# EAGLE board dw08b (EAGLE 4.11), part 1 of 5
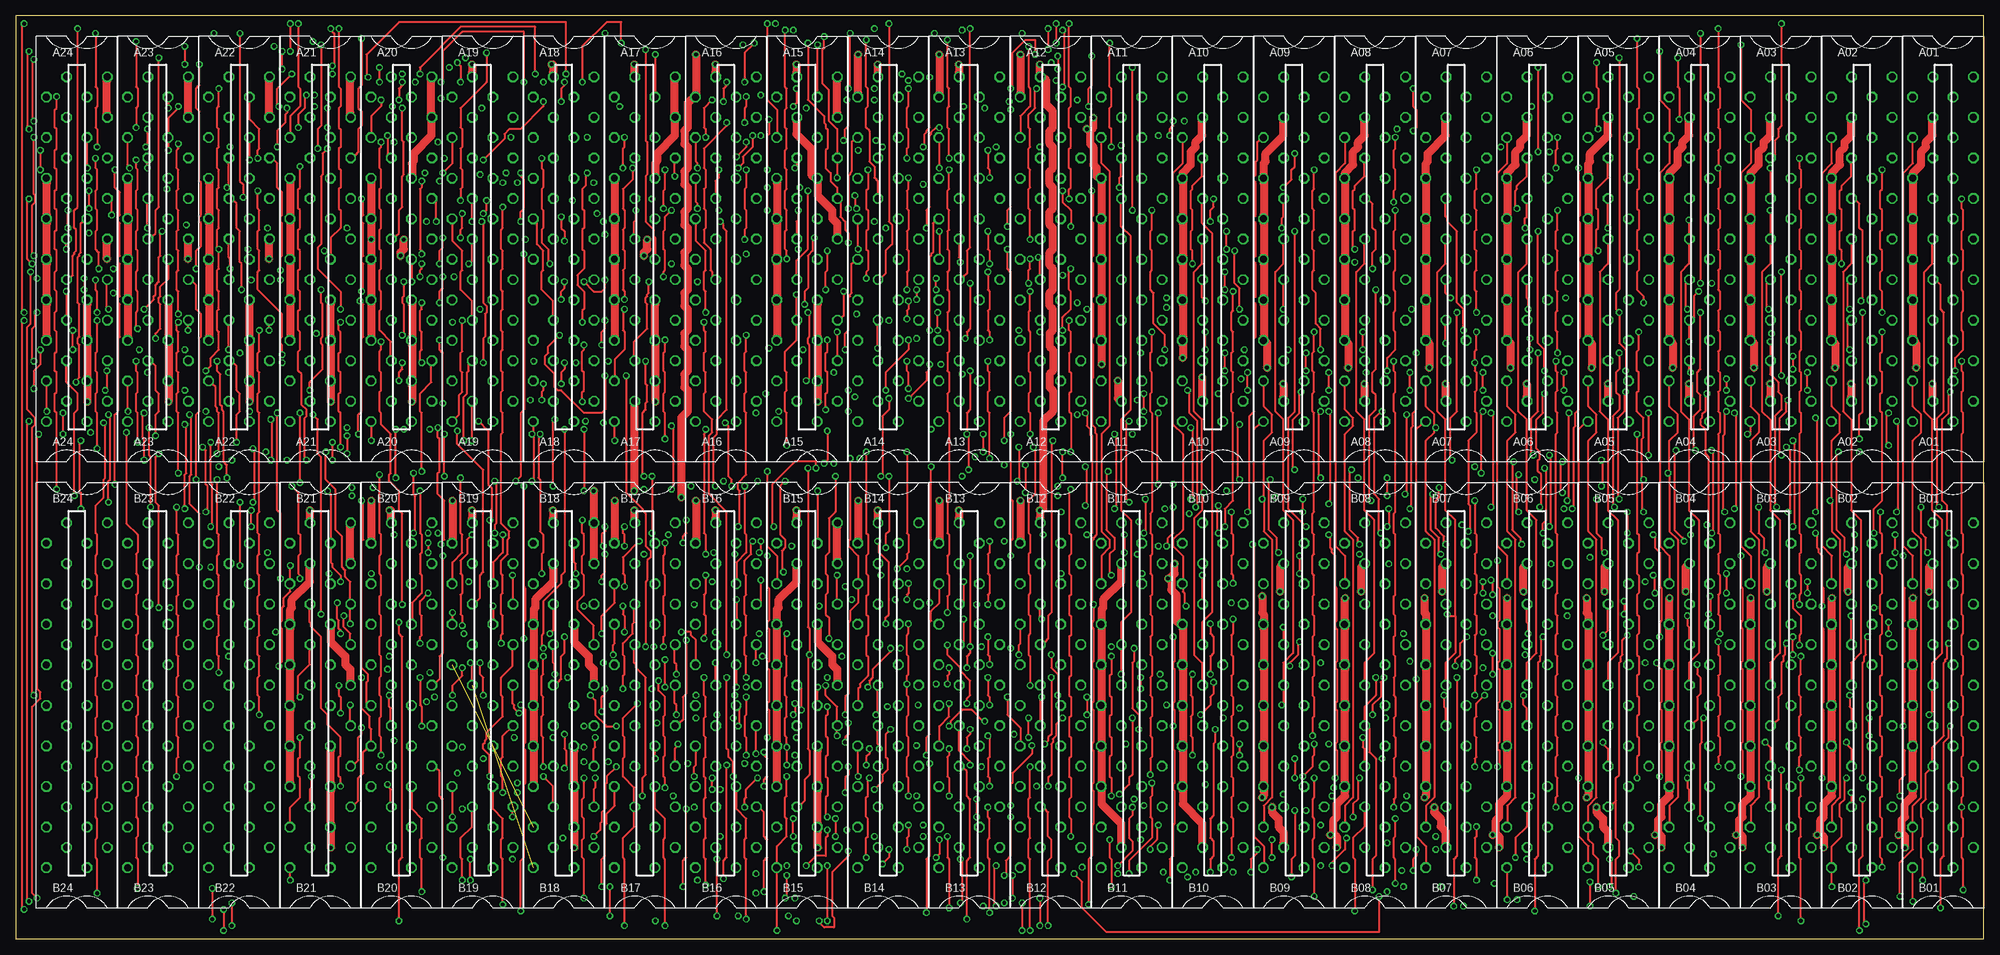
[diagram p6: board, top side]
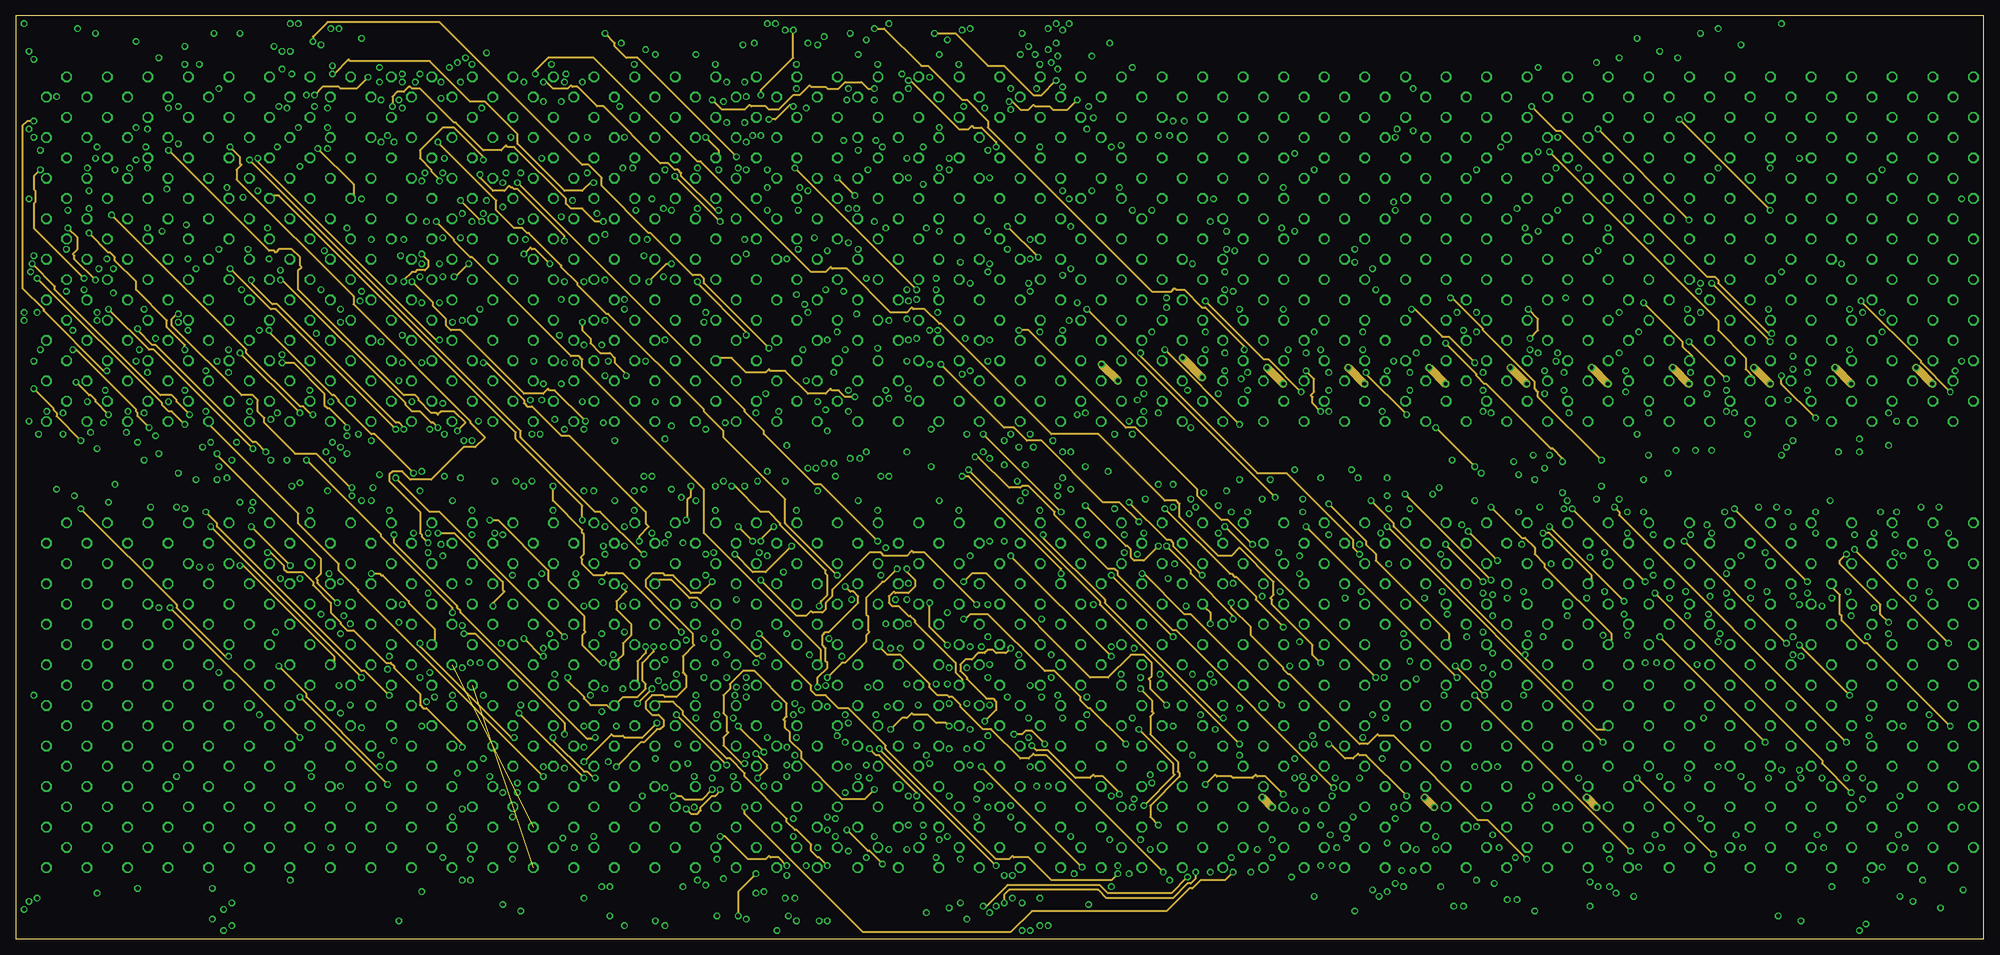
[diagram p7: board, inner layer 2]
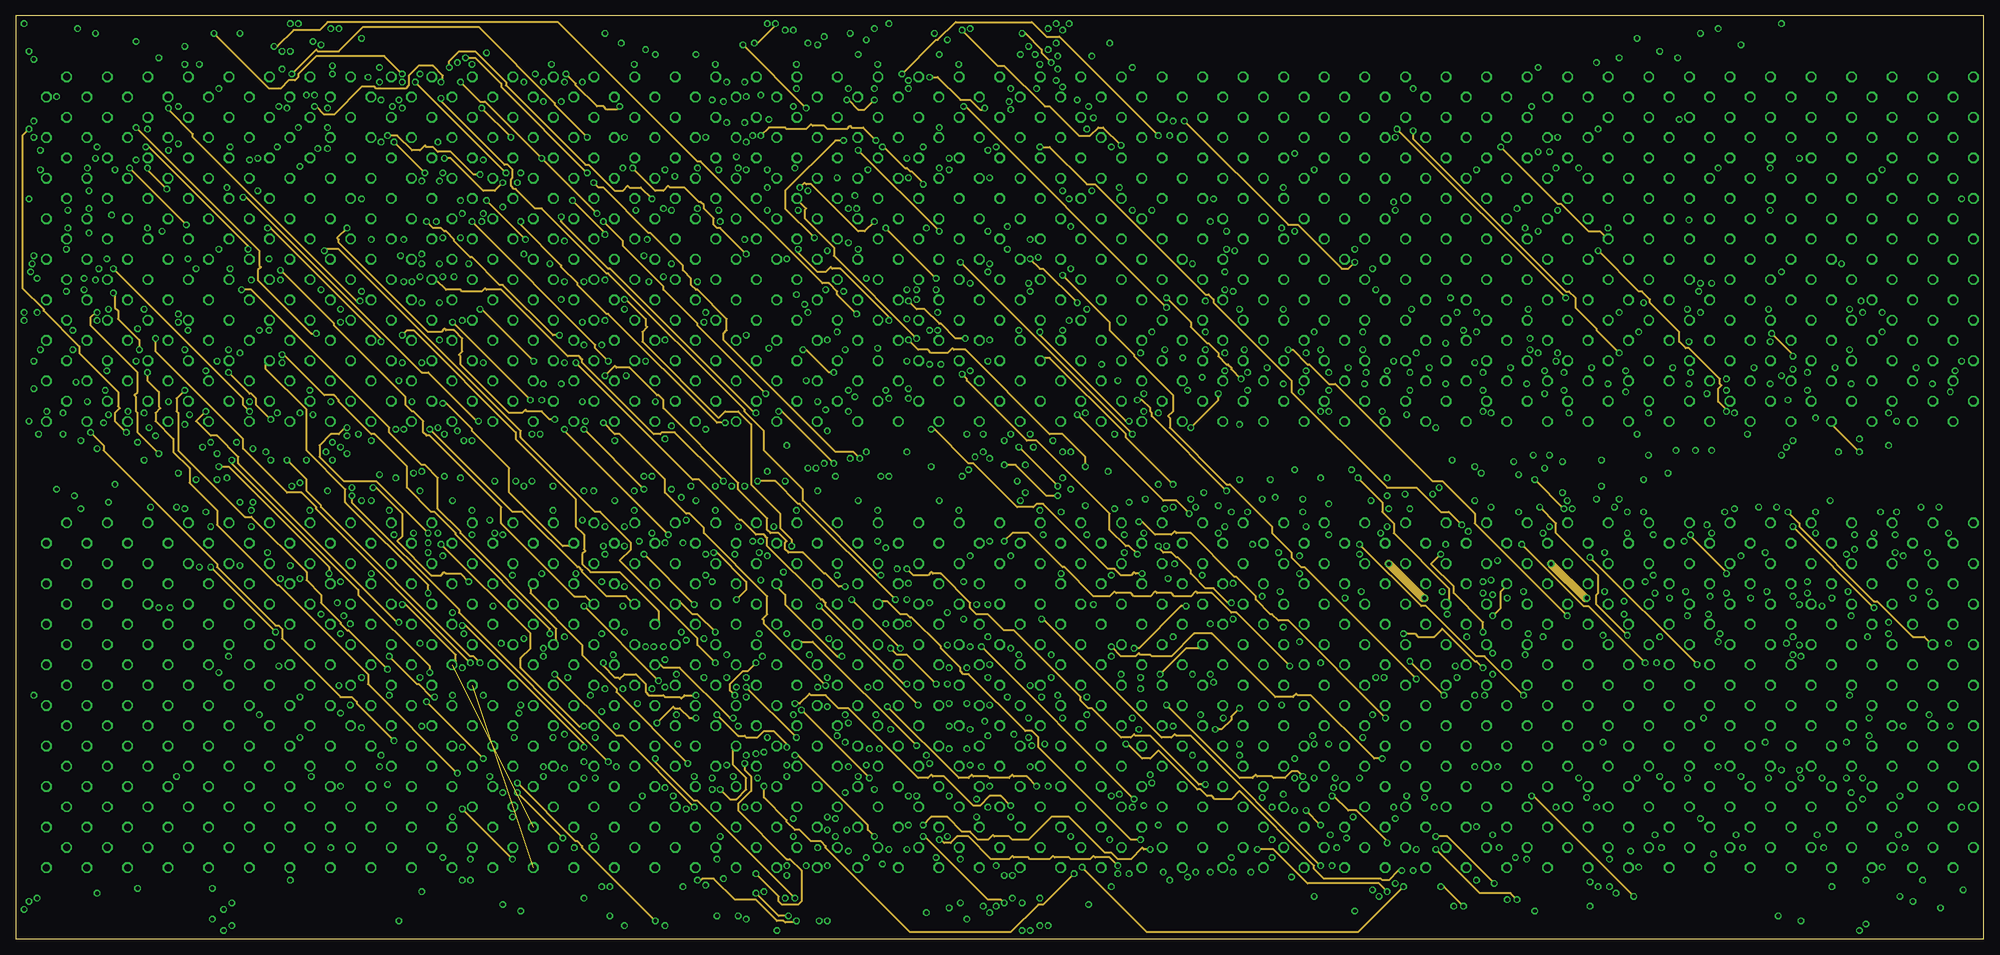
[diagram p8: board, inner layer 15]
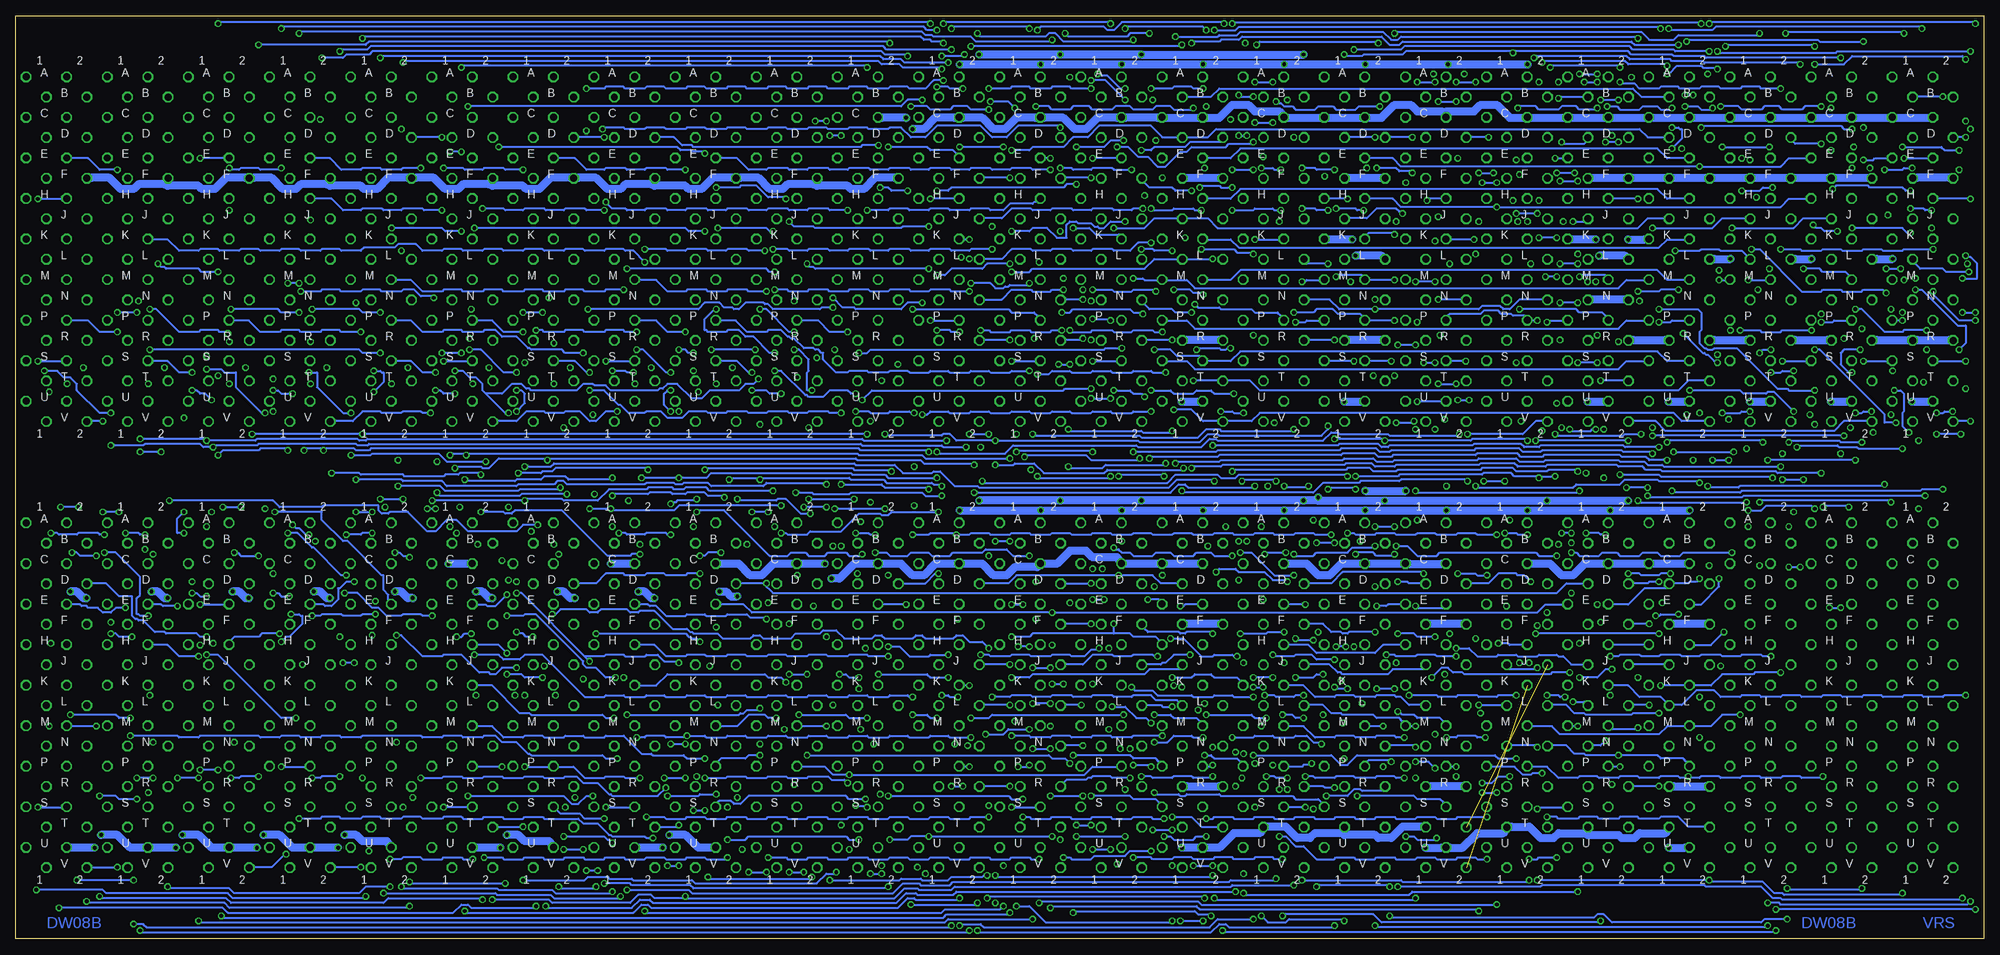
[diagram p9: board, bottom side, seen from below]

Size 307.98 x 144.46 mm. Coordinates in mm from the lower left corner, seen from the top.
Outline: 0,0 307.98,0 307.98,144.46 0,144.46 0,0
Copper layers (1*2*15*16): Top 0.035mm / dielectric 1.5mm / 2 0.035mm / dielectric 0.15mm / 15 0.035mm / dielectric 0.2mm / Bottom 0.035mm
Design rules "10mils": minimum track width 12mil, minimum drill 24mil, track to track 10mil, track to pad 10mil, pad to pad 10mil, via to via 10mil, smd to smd 10mil, copper to edge 25mil, drill to drill 10mil, minimum pad ring 10mil, minimum via ring 8mil, stop-mask expansion 0mil, vias tented up to drill 0mil, thermal gap 10mil
Net classes: 1 supply: width 1.27 mm

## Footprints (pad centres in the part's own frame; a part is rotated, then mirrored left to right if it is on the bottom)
H807 = drill 1.092 octagon: A1 4.763,28.575; A2 -1.587,28.575; B1 1.587,25.4; B2 -4.763,25.4; C1 4.763,22.225; C2 -1.587,22.225; D1 1.587,19.05; D2 -4.763,19.05; E1 4.763,15.875; E2 -1.587,15.875; F1 1.587,12.7; F2 -4.763,12.7; H1 4.763,9.525; H2 -1.587,9.525; J1 1.587,6.35; J2 -4.763,6.35; K1 4.763,3.175; K2 -1.587,3.175; L1 1.587,0; L2 -4.763,0; M1 4.763,-3.175; M2 -1.587,-3.175; N1 1.587,-6.35; N2 -4.763,-6.35; P1 4.763,-9.525; P2 -1.587,-9.525; R1 1.587,-12.7; R2 -4.763,-12.7; S1 4.763,-15.875; S2 -1.587,-15.875; T1 1.587,-19.05; T2 -4.763,-19.05; U1 4.763,-22.225; U2 -1.587,-22.225; V1 1.587,-25.4; V2 -4.763,-25.4

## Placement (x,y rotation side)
A01  W011  [H807]  301.62,106.36 0 top
A02  W011  [H807]  288.93,106.36 0 top
A03  W011  [H807]  276.23,106.36 0 top
A04  W011  [H807]  263.52,106.36 0 top
A05  W011  [H807]  250.82,106.36 0 top
A06  W011  [H807]  238.12,106.36 0 top
A07  W011  [H807]  225.43,106.36 0 top
A08  W011  [H807]  212.72,106.36 0 top
A09  W011  [H807]  200.03,106.36 0 top
A10  W011  [H807]  187.32,106.36 0 top
A11  W011  [H807]  174.62,106.36 0 top
A12  M508  [H807]  161.93,106.36 0 top
A13  M508  [H807]  149.22,106.36 0 top
A14  M508  [H807]  136.53,106.36 0 top
A15  M906  [H807]  123.83,106.36 0 top
A16  M508  [H807]  111.12,106.36 0 top
A17  M906  [H807]  98.42,106.36 0 top
A18  M660  [H807]  85.72,106.36 0 top
A19  M660  [H807]  73.03,106.36 0 top
A20  M903  [H807]  60.33,106.36 0 top
A21  M903  [H807]  47.62,106.36 0 top
A22  M903  [H807]  34.92,106.36 0 top
A23  M903  [H807]  22.23,106.36 0 top
A24  M903  [H807]  9.53,106.36 0 top
B01  W011  [H807]  301.62,36.51 0 top
B02  W011  [H807]  288.93,36.51 0 top
B03  W011  [H807]  276.23,36.51 0 top
B04  W011  [H807]  263.52,36.51 0 top
B05  W011  [H807]  250.82,36.51 0 top
B06  W011  [H807]  238.12,36.51 0 top
B07  W011  [H807]  225.43,36.51 0 top
B08  W011  [H807]  212.72,36.51 0 top
B09  W011  [H807]  200.03,36.51 0 top
B10  W011  [H807]  187.32,36.51 0 top
B11  W011  [H807]  174.62,36.51 0 top
B12  M508  [H807]  161.93,36.51 0 top
B13  M508  [H807]  149.22,36.51 0 top
B14  M508  [H807]  136.53,36.51 0 top
B15  M906  [H807]  123.83,36.51 0 top
B16  M051  [H807]  111.12,36.51 0 top
B17  M051  [H807]  98.42,36.51 0 top
B18  M906  [H807]  85.72,36.51 0 top
B19  M051  [H807]  73.03,36.51 0 top
B20  M051  [H807]  60.33,36.51 0 top
B21  M906  [H807]  47.62,36.51 0 top
B22  H807  [H807]  34.92,36.51 0 top
B23  H807  [H807]  22.23,36.51 0 top
B24  H807  [H807]  9.53,36.51 0 top

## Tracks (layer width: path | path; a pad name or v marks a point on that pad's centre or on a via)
-15V  (via drill 0.61)
  Top 1.27: v106.43,138.43 106.43,132.33 A16.B2 105.66,131.32 105.16,130.81 105.16,127 104.65,126.49 104.65,124.46 105.16,123.95 105.16,120.65 104.65,120.14 104.65,118.11 105.16,117.6 105.16,114.3 104.65,113.79 104.65,111.76 105.16,111.25 105.16,107.95 104.65,107.44 104.65,105.41 105.16,104.9 105.16,101.6 104.65,101.09 104.65,99.06 105.16,98.55 105.16,95.25 104.65,94.74 104.65,92.71 105.16,92.2 105.16,88.9 104.65,88.39 104.65,86.36 105.16,85.85 105.16,82.55 104.14,81.53 v104.14,69.09 | v131.83,138.43 131.83,132.33 A14.B2 | v144.53,138.43 144.53,132.33 A13.B2 | v157.23,138.43 157.23,132.33 A12.B2 | v55.63,68.58 55.63,62.48 B20.B2 | v68.33,68.58 68.33,62.48 B19.B2 | v93.73,68.58 93.73,62.48 B17.B2 | v106.43,68.58 106.43,62.48 B16.B2 | v131.83,68.58 131.83,62.48 B14.B2 | v144.53,68.58 144.53,62.48 B13.B2 | v157.23,68.58 157.23,62.48 B12.B2
  Bottom 1.27: v106.43,138.43 v131.83,138.43 v144.53,138.43 v157.23,138.43 | v55.63,68.58 v68.33,68.58 v93.73,68.58 104.14,68.58 | 104.14,68.58 v106.43,68.58 v131.83,68.58 v144.53,68.58 v157.23,68.58 | v104.14,69.09 104.14,68.58
GND  (via drill 0.61)
  Top 1.27: B15.A1 128.52,64.52 128.52,59.44 B15.C1 | B15.K1 128.52,40.39 128.52,42.16 127.76,42.93 127.76,44.2 125.48,46.48 125.48,48.51 B15.F1 | v125.48,14.22 125.48,16.76 B15.T1 125.48,18.03 125.48,23.11 B15.R1 125.48,24.38 125.48,29.46 B15.N1 | B15.R2 119.13,24.38 119.13,29.46 B15.N2 119.13,30.73 119.13,35.81 B15.L2 119.13,37.08 119.13,42.16 B15.J2 119.13,43.43 119.13,48.51 B15.F2 119.13,49.78 119.13,51.56 119.38,51.82 119.38,53.09 122.17,55.88 122.17,58.17 B15.C2 | B21.A1 52.32,64.52 52.32,59.44 B21.C1 | B21.K1 52.32,40.39 52.32,42.16 51.56,42.93 51.56,44.2 49.28,46.48 49.28,48.51 B21.F1 | v49.28,14.22 49.28,16.76 B21.T1 49.28,18.03 49.28,23.11 B21.R1 49.28,24.38 49.28,29.46 B21.N1 | B21.R2 42.93,24.38 42.93,29.46 B21.N2 42.93,30.73 42.93,35.81 B21.L2 42.93,37.08 42.93,42.16 B21.J2 42.93,43.43 42.93,48.51 B21.F2 42.93,49.78 42.93,51.56 43.18,51.82 43.18,53.09 45.97,55.88 45.97,58.17 B21.C2 | B18.C1 90.42,59.44 90.42,64.52 B18.A1 90.42,65.79 v90.42,70.1 | B18.K1 90.42,40.39 90.42,42.16 89.66,42.93 89.66,44.2 87.38,46.48 87.38,48.51 B18.F1 | v87.38,14.22 87.38,16.76 B18.T1 87.38,18.03 87.38,23.11 B18.R1 87.38,24.38 87.38,29.46 B18.N1 | B18.R2 81.03,24.38 81.03,29.46 B18.N2 81.03,30.73 81.03,35.81 B18.L2 81.03,37.08 81.03,42.16 B18.J2 81.03,43.43 81.03,48.51 B18.F2 81.03,49.78 81.03,51.56 81.28,51.82 81.28,53.09 84.07,55.88 84.07,58.17 B18.C2 | v295.66,14.22 295.66,16 295.15,16.51 | 295.15,16.51 295.15,18.54 295.66,19.05 295.66,21.08 296.93,22.35 296.93,23.11 B01.R2 296.93,24.38 296.93,29.46 B01.N2 296.93,30.73 296.93,35.81 B01.L2 296.93,37.08 296.93,42.16 B01.J2 296.93,43.43 296.93,48.51 B01.F2 296.93,49.78 v296.93,53.34
  Top 1.27: v299.47,54.36 299.47,58.17 B01.C2 | v282.96,14.22 282.96,16 282.45,16.51 | 282.45,16.51 282.45,18.54 282.96,19.05 282.96,21.08 284.23,22.35 284.23,23.11 B02.R2 284.23,24.38 284.23,29.46 B02.N2 284.23,30.73 284.23,35.81 B02.L2 284.23,37.08 284.23,42.16 B02.J2 284.23,43.43 284.23,48.51 B02.F2 284.23,49.78 v284.23,53.34 | v286.77,54.36 286.77,58.17 B02.C2 | v270.26,14.22 270.26,16 269.75,16.51 | 269.75,16.51 269.75,18.54 270.26,19.05 270.26,21.08 271.53,22.35 271.53,23.11 B03.R2 271.53,24.38 271.53,29.46 B03.N2 271.53,30.73 271.53,35.81 B03.L2 271.53,37.08 271.53,42.16 B03.J2 271.53,43.43 271.53,48.51 B03.F2 271.53,49.78 v271.53,53.34 | v274.07,54.36 274.07,58.17 B03.C2 | v247.4,20.57 247.4,19.81 248.41,18.8 248.41,17.53 249.17,16.76 249.17,14.99 B05.U2 | v245.87,22.1 246.13,22.35 246.13,23.11 B05.R2 246.13,24.38 246.13,29.46 B05.N2 246.13,30.73 246.13,35.81 B05.L2 246.13,37.08 246.13,42.16 B05.J2 246.13,43.43 246.13,48.51 B05.F2 246.13,49.78 246.13,50.8 245.87,51.05 v245.87,53.34 | v248.67,54.36 248.67,58.17 B05.C2 | v257.56,14.22 257.56,16 257.05,16.51 | 257.05,16.51 257.05,18.54 257.56,19.05 257.56,21.08 258.83,22.35 258.83,23.11 B04.R2 258.83,24.38 258.83,29.46 B04.N2 258.83,30.73 258.83,35.81 B04.L2 258.83,37.08 258.83,42.16 B04.J2 258.83,43.43 258.83,48.51 B04.F2 258.83,49.78 v258.83,53.34 | v261.37,54.36 261.37,58.17 B04.C2 | v256.54,16.26 257.05,16.51 | v269.24,16.26 269.75,16.51 | v281.94,16.26 282.45,16.51 | v294.64,16.26 295.15,16.51 | B11.U2 172.97,14.99 172.97,18.03 169.93,21.08 169.93,23.11 B11.R2 169.93,24.38 169.93,29.46 B11.N2 169.93,30.73 169.93,35.81 B11.L2 169.93,37.08 169.93,42.16 B11.J2 169.93,43.43 169.93,48.51 B11.F2 169.93,49.78 169.93,51.56 170.18,51.82 170.18,53.09 172.97,55.88 172.97,58.17 B11.C2
  Top 1.27: v222,20.57 222,19.81 223.01,18.8 223.01,17.53 223.77,16.76 223.77,14.99 B07.U2 | v220.47,22.1 220.73,22.35 220.73,23.11 B07.R2 220.73,24.38 220.73,29.46 B07.N2 220.73,30.73 220.73,35.81 B07.L2 220.73,37.08 220.73,42.16 B07.J2 220.73,43.43 220.73,48.51 B07.F2 220.73,49.78 220.73,50.8 220.47,51.05 v220.47,53.34 | v223.27,54.36 223.27,58.17 B07.C2 | v232.16,14.22 232.16,16 231.65,16.51 | 231.65,16.51 231.65,18.54 232.16,19.05 232.16,21.08 233.43,22.35 233.43,23.11 B06.R2 233.43,24.38 233.43,29.46 B06.N2 233.43,30.73 233.43,35.81 B06.L2 233.43,37.08 233.43,42.16 B06.J2 233.43,43.43 233.43,48.51 B06.F2 233.43,49.78 v233.43,53.34 | v235.97,54.36 235.97,58.17 B06.C2 | v231.14,16.26 231.65,16.51 | v206.76,14.22 206.76,16 206.25,16.51 | 206.25,16.51 206.25,18.54 206.76,19.05 206.76,21.08 208.03,22.35 208.03,23.11 B08.R2 208.03,24.38 208.03,29.46 B08.N2 208.03,30.73 208.03,35.81 B08.L2 208.03,37.08 208.03,42.16 B08.J2 208.03,43.43 208.03,48.51 B08.F2 208.03,49.78 v208.03,53.34 | v210.57,54.36 210.57,58.17 B08.C2 | B10.U2 185.67,14.99 185.67,18.03 182.63,21.08 182.63,23.11 B10.R2 182.63,24.38 182.63,29.46 B10.N2 182.63,30.73 182.63,35.81 B10.L2 182.63,37.08 182.63,42.16 B10.J2 182.63,43.43 182.63,48.51 B10.F2 181.86,49.53 181.61,49.78 181.61,53.85 180.85,54.61 180.85,56.39 | v196.6,20.57 196.6,19.81 197.61,18.8 197.61,17.53 198.37,16.76 198.37,14.99 B09.U2 | v195.07,22.1 195.33,22.35 195.33,23.11 B09.R2 195.33,24.38 195.33,29.46 B09.N2 195.33,30.73 195.33,35.81 B09.L2 195.33,37.08 195.33,42.16 B09.J2 195.33,43.43 195.33,48.51 B09.F2 195.33,49.78 195.33,50.8 195.07,51.05 v195.07,53.59
  Top 1.27: v197.87,54.36 197.87,58.17 B09.C2 | 180.85,56.39 180.85,56.64 181.36,57.15 v181.36,58.67 | v205.74,16.26 206.25,16.51 | v180.34,56.39 180.85,56.39 | A17.A1 103.12,134.37 103.12,129.29 A17.C1 103.12,128.02 103.12,125.73 100.33,122.94 100.33,121.67 100.08,121.41 100.08,119.63 A17.F1 | v100.08,84.07 100.08,86.61 A17.T1 100.08,87.88 100.08,92.96 A17.R1 100.08,94.23 100.08,99.31 A17.N1 | A17.R2 93.73,94.23 93.73,99.31 A17.N2 93.73,100.58 93.73,105.66 A17.L2 93.73,106.93 93.73,112.01 A17.J2 93.73,113.28 93.73,118.36 A17.F2 | v98.81,109.47 98.81,107.95 98.3,107.44 v98.3,106.93 | A24.A1 14.22,134.37 14.22,129.29 A24.C1 | A23.A1 26.92,134.37 26.92,129.29 A23.C1 | A22.A1 39.62,134.37 39.62,129.29 A22.C1 | A21.A1 52.32,134.37 52.32,129.29 A21.C1 | A20.A1 65.02,134.37 65.02,129.29 A20.C1 65.02,128.02 65.02,125.73 62.23,122.94 62.23,121.67 61.98,121.41 61.98,119.63 A20.F1 | A20.F2 55.63,118.36 55.63,113.28 A20.J2 55.63,112.01 v55.63,109.47 55.63,106.93 A20.L2 55.63,105.66 55.63,100.58 A20.N2 55.63,99.31 55.63,94.23 A20.R2 | v61.98,84.07 61.98,86.61 A20.T1 61.98,87.88 61.98,92.96 A20.R1 61.98,94.23 61.98,99.31 A20.N1 | v49.28,84.07 49.28,86.61 A21.T1 49.28,87.88 49.28,92.96 A21.R1 49.28,94.23 49.28,99.31 A21.N1 | v60.71,109.47 60.71,107.95 60.2,107.44 v60.2,106.93 | v36.58,84.07 36.58,86.61 A22.T1 36.58,87.88 36.58,92.96 A22.R1 36.58,94.23 36.58,99.31 A22.N1 | A21.R2 42.93,94.23 42.93,99.31 A21.N2 42.93,100.58 42.93,105.66 A21.L2 42.93,106.93 42.93,112.01 A21.J2 42.93,113.28 42.93,118.36 A21.F2 | v39.62,106.43 39.62,108.97 A22.K1 | v23.88,84.07 23.88,86.61 A23.T1 23.88,87.88 23.88,92.96 A23.R1 23.88,94.23 23.88,99.31 A23.N1
  Top 1.27: A22.R2 30.23,94.23 30.23,99.31 A22.N2 30.23,100.58 30.23,105.66 A22.L2 30.23,106.93 30.23,112.01 A22.J2 30.23,113.28 30.23,118.36 A22.F2 | v26.92,106.43 26.92,108.97 A23.K1 | v11.18,84.07 11.18,86.61 A24.T1 11.18,87.88 11.18,92.96 A24.R1 11.18,94.23 11.18,99.31 A24.N1 | A24.R2 4.83,94.23 4.83,99.31 A24.N2 4.83,100.58 4.83,105.66 A24.L2 4.83,106.93 4.83,112.01 A24.J2 4.83,113.28 4.83,118.36 A24.F2 | A23.R2 17.53,94.23 17.53,99.31 A23.N2 17.53,100.58 17.53,105.66 A23.L2 17.53,106.93 17.53,112.01 A23.J2 17.53,113.28 17.53,118.36 A23.F2 | v14.22,106.43 14.22,108.97 A24.K1 | v287.27,86.87 287.27,84.84 A02.U2 | v284.73,89.41 284.73,93.22 A02.R2 284.23,94.23 284.23,99.31 A02.N2 284.23,100.58 284.23,105.66 A02.L2 284.23,106.93 284.23,112.01 A02.J2 284.23,113.28 284.23,118.36 A02.F2 284.23,119.63 284.23,119.89 285.5,121.16 285.5,123.19 286.26,123.95 286.26,124.71 287.27,125.73 287.27,128.02 A02.C2 | v299.97,86.87 299.97,84.84 A01.U2 | v297.43,89.41 297.43,93.22 A01.R2 296.93,94.23 296.93,99.31 A01.N2 296.93,100.58 296.93,105.66 A01.L2 296.93,106.93 296.93,112.01 A01.J2 296.93,113.28 296.93,118.36 A01.F2 296.93,119.63 296.93,119.89 298.2,121.16 298.2,123.19 298.96,123.95 298.96,124.71 299.97,125.73 299.97,128.02 A01.C2 | v261.87,86.87 261.87,84.84 A04.U2 | v259.33,89.41 259.33,93.22 A04.R2 258.83,94.23 258.83,99.31 A04.N2 258.83,100.58 258.83,105.66 A04.L2 258.83,106.93 258.83,112.01 A04.J2 258.83,113.28 258.83,118.36 A04.F2 258.83,119.63 258.83,119.89 260.1,121.16 260.1,123.19 260.86,123.95 260.86,124.71 261.87,125.73 261.87,128.02 A04.C2
  Top 1.27: v274.57,86.87 274.57,84.84 A03.U2 | v272.03,89.41 272.03,93.22 A03.R2 271.53,94.23 271.53,99.31 A03.N2 271.53,100.58 271.53,105.66 A03.L2 271.53,106.93 271.53,112.01 A03.J2 271.53,113.28 271.53,118.36 A03.F2 271.53,119.63 271.53,119.89 272.8,121.16 272.8,123.19 273.56,123.95 273.56,124.71 274.57,125.73 274.57,128.02 A03.C2 | v236.47,86.87 236.47,84.84 A06.U2 | v233.93,89.41 233.93,93.22 A06.R2 233.43,94.23 233.43,99.31 A06.N2 233.43,100.58 233.43,105.66 A06.L2 233.43,106.93 233.43,112.01 A06.J2 233.43,113.28 233.43,118.36 A06.F2 233.43,119.63 233.43,119.89 234.7,121.16 234.7,123.19 235.46,123.95 235.46,124.71 236.47,125.73 236.47,128.02 A06.C2 | v249.17,86.87 249.17,84.84 A05.U2 | v246.63,89.41 246.63,93.22 A05.R2 246.13,94.23 246.13,99.31 A05.N2 246.13,100.58 246.13,105.66 A05.L2 246.13,106.93 246.13,112.01 A05.J2 246.13,113.28 246.13,118.36 A05.F2 246.13,119.63 246.13,121.41 246.38,121.67 246.38,122.94 249.17,125.73 249.17,128.02 A05.C2 | v211.07,86.87 211.07,84.84 A08.U2 | v208.53,89.41 208.53,93.22 A08.R2 208.03,94.23 208.03,99.31 A08.N2 208.03,100.58 208.03,105.66 A08.L2 208.03,106.93 208.03,112.01 A08.J2 208.03,113.28 208.03,118.36 A08.F2 208.03,119.63 208.03,119.89 209.3,121.16 209.3,123.19 210.06,123.95 210.06,124.71 211.07,125.73 211.07,128.02 A08.C2 | v223.77,86.87 223.77,84.84 A07.U2 | v221.23,89.41 221.23,93.22 A07.R2 220.73,94.23 220.73,99.31 A07.N2 220.73,100.58 220.73,105.66 A07.L2 220.73,106.93 220.73,112.01 A07.J2 220.73,113.28 220.73,118.36 A07.F2 220.73,119.63 220.73,121.41 220.98,121.67 220.98,122.94 223.77,125.73 223.77,128.02 A07.C2
  Top 1.27: v185.67,87.88 185.67,84.84 A10.U2 | v182.63,90.93 182.63,92.96 A10.R2 182.63,94.23 182.63,99.31 A10.N2 182.63,100.58 182.63,105.66 A10.L2 182.63,106.93 182.63,112.01 A10.J2 182.63,113.28 182.63,118.36 A10.F2 182.63,119.63 182.63,119.89 183.9,121.16 183.9,123.19 184.66,123.95 184.66,124.71 185.67,125.73 185.67,128.02 A10.C2 | v198.37,86.87 198.37,84.84 A09.U2 | v195.83,89.41 195.83,93.22 A09.R2 195.33,94.23 195.33,99.31 A09.N2 195.33,100.58 195.33,105.66 A09.L2 195.33,106.93 195.33,112.01 A09.J2 195.33,113.28 195.33,118.36 A09.F2 195.33,119.63 195.33,121.41 195.58,121.67 195.58,122.94 198.37,125.73 198.37,128.02 A09.C2 | v172.47,87.38 172.47,84.58 A11.U2 | v169.93,89.92 169.93,92.96 A11.R2 169.93,94.23 169.93,99.31 A11.N2 169.93,100.58 169.93,105.66 A11.L2 169.93,106.93 169.93,112.01 A11.J2 169.93,113.28 169.93,118.36 A11.F2 169.16,119.38 169.16,120.65 168.66,121.16 168.66,123.95 168.15,124.46 168.15,126.49 | v168.66,128.52 168.66,127 168.15,126.49 | A15.K1 128.52,110.24 128.52,112.01 127.76,112.78 127.76,114.05 125.48,116.33 125.48,118.36 A15.F1 124.71,119.38 124.46,119.63 124.46,123.7 122.17,125.98 122.17,128.02 A15.C2 | v125.48,84.07 125.48,86.61 A15.T1 125.48,87.88 125.48,92.96 A15.R1 125.48,94.23 125.48,99.31 A15.N1 | A15.R2 119.13,94.23 119.13,99.31 A15.N2 119.13,100.58 119.13,105.66 A15.L2 119.13,106.93 119.13,112.01 A15.J2 119.13,113.28 119.13,118.36 A15.F2 | A15.A1 128.52,134.37 128.52,129.29 A15.C1 | v167.64,126.75 168.15,126.49 | v96.77,70.1 96.77,83.57 A17.U2
  2 1.27: v245.87,22.1 v247.4,20.57 | v220.47,22.1 v222,20.57 | v195.07,22.1 v196.6,20.57 | v284.73,89.41 v287.27,86.87 | v297.43,89.41 v299.97,86.87 | v259.33,89.41 v261.87,86.87 | v272.03,89.41 v274.57,86.87 | v233.93,89.41 v236.47,86.87 | v246.63,89.41 v249.17,86.87 | v208.53,89.41 v211.07,86.87 | v221.23,89.41 v223.77,86.87 | v182.63,90.93 v185.67,87.88 | v195.83,89.41 v198.37,86.87 | v169.93,89.92 v172.47,87.38
  15 1.27: v214.88,58.67 220.22,53.34 v220.47,53.34 | v240.28,58.67 245.62,53.34 v245.87,53.34
  Bottom 1.27: B15.C2 122.94,58.67 128.02,58.67 B15.C1 129.29,58.67 134.37,58.67 B14.C2 135.38,59.44 135.64,59.69 139.45,59.69 140.46,60.71 143,60.71 145.03,58.67 147.07,58.67 B13.C2 148.08,58.17 151.64,58.17 152.91,56.9 154.94,56.9 156.72,58.67 159.77,58.67 B12.C2 161.04,58.67 164.08,58.67 165.86,56.9 167.64,56.9 169.42,58.67 172.47,58.67 B11.C2 173.74,58.67 176.78,58.67 179.07,56.39 v180.34,56.39 | 100.46,16.64 100.58,16.51 104.65,16.51 105.41,15.75 107.44,15.75 109.22,17.53 112.01,17.53 B16.T1 113.03,16.76 113.28,16.51 117.35,16.51 119.63,14.22 121.67,14.22 B15.U2 122.94,14.22 v125.48,14.22 | 100.46,16.64 100.33,16.76 B17.T1 | B15.R2 119.63,23.88 124.71,23.88 B15.R1 | B15.F1 124.71,49.28 119.63,49.28 B15.F2 | B21.C2 46.74,58.67 51.82,58.67 B21.C1 53.09,58.67 58.17,58.67 B20.C2 59.44,58.67 62.48,58.67 64.26,56.9 66.04,56.9 67.82,58.67 70.87,58.67 B19.C2 | v49.28,14.22 46.74,14.22 B21.U2 | B21.R2 43.43,23.88 48.51,23.88 B21.R1 | B21.F1 48.51,49.28 43.43,49.28 B21.F2 | B18.C2 84.84,58.67 89.92,58.67 B18.C1 91.19,58.67 96.27,58.67 B17.C2 97.54,58.67 100.58,58.67 102.36,56.9 104.14,56.9 105.92,58.67 108.97,58.67 B16.C2 | 62.36,16.64 62.48,16.51 66.55,16.51 67.31,15.75 69.34,15.75 71.12,17.53 73.91,17.53 B19.T1 74.93,16.76 75.18,16.51 79.25,16.51 81.53,14.22 83.57,14.22 B18.U2 84.84,14.22 v87.38,14.22 | 62.36,16.64 62.23,16.76 B20.T1 | B18.R2 81.53,23.88 86.61,23.88 B18.R1 | B18.F1 86.61,49.28 81.53,49.28 B18.F2 | B21.T1 49.53,16.76 49.78,16.51 53.85,16.51 54.61,15.75 56.64,15.75 57.15,16.26 61.98,16.26 62.36,16.64 | 100.46,16.64 100.08,16.26 95.25,16.26 94.74,15.75 92.71,15.75 90.93,17.53 87.88,17.53 B18.T1
  Bottom 1.27: v295.66,14.22 299.47,14.22 B01.U2 | v299.47,54.36 298.45,54.36 297.43,53.34 v296.93,53.34 | v282.96,14.22 286.77,14.22 B02.U2 288.04,14.22 290.07,14.22 292.1,16.26 v294.64,16.26 | v286.77,54.36 285.75,54.36 284.73,53.34 v284.23,53.34 | v270.26,14.22 274.07,14.22 B03.U2 275.34,14.22 277.37,14.22 279.4,16.26 v281.94,16.26 | v274.07,54.36 273.05,54.36 272.03,53.34 v271.53,53.34 | v248.67,54.36 247.65,54.36 246.63,53.34 v245.87,53.34 | v257.56,14.22 261.37,14.22 B04.U2 262.64,14.22 264.67,14.22 266.7,16.26 v269.24,16.26 | v261.37,54.36 260.35,54.36 259.33,53.34 v258.83,53.34 | v256.54,16.26 254.76,16.26 253.75,15.24 249.94,15.24 249.68,14.99 B05.U2 | v223.27,54.36 222.25,54.36 221.23,53.34 v220.47,53.34 | v232.16,14.22 235.97,14.22 B06.U2 | v235.97,54.36 234.95,54.36 233.93,53.34 v233.43,53.34 | v231.14,16.26 229.36,16.26 228.35,15.24 224.54,15.24 224.28,14.99 B07.U2 | v206.76,14.22 210.57,14.22 B08.U2 | v210.57,54.36 209.55,54.36 208.53,53.34 v208.03,53.34 | B09.C2 197.87,58.67 194.82,58.67 193.04,56.9 191.26,56.9 189.48,58.67 186.44,58.67 B10.C2 185.17,58.67 v181.36,58.67 | v197.87,54.36 196.85,54.36 196.09,53.59 v195.07,53.59 | v205.74,16.26 203.2,16.26 201.17,14.22 199.14,14.22 B09.U2 | v214.88,58.67 211.84,58.67 B08.C2 | v240.28,58.67 237.24,58.67 B06.C2 | 84.58,129.29 84.84,129.54 88.65,129.54 89.66,130.56 92.2,130.56 94.23,128.52 96.27,128.52 A17.C2 97.54,128.52 102.62,128.52 A17.C1 103.89,128.52 108.97,128.52 A16.C2 109.98,129.29 110.24,129.54 114.05,129.54 115.06,130.56 117.6,130.56 119.63,128.52 121.67,128.52 A15.C2 122.94,128.52 128.02,128.52 A15.C1 129.29,128.52 134.37,128.52 A14.C2 135.64,128.52 138.68,128.52 140.46,126.75 142.24,126.75 144.02,128.52 147.07,128.52 A13.C2 148.34,128.52 151.38,128.52 153.16,126.75 154.94,126.75 156.72,128.52 159.77,128.52 A12.C2 161.04,128.52 164.08,128.52 165.86,126.75 v167.64,126.75
  Bottom 1.27: 84.58,129.29 A18.C2 | v100.08,84.07 97.54,84.07 A17.U2 | A17.R2 94.23,93.73 99.31,93.73 A17.R1 | v98.81,109.47 102.62,109.47 A17.K1 | v98.3,106.93 94.23,106.93 A17.L2 | A17.F1 99.31,119.13 94.23,119.13 A17.F2 | A24.C2 8.64,128.52 13.72,128.52 A24.C1 14.99,128.52 20.07,128.52 A23.C2 21.34,128.52 26.42,128.52 A23.C1 27.69,128.52 32.77,128.52 A22.C2 34.04,128.52 39.12,128.52 A22.C1 40.39,128.52 45.47,128.52 A21.C2 46.74,128.52 51.82,128.52 A21.C1 53.09,128.52 58.17,128.52 A20.C2 59.44,128.52 64.52,128.52 A20.C1 65.79,128.52 70.87,128.52 A19.C2 72.14,128.52 74.17,128.52 76.2,130.56 78.74,130.56 79.76,129.54 84.07,129.54 84.58,129.29 | v55.63,109.47 53.09,109.47 A21.K1 | A20.F1 61.21,119.13 56.13,119.13 A20.F2 54.86,119.13 49.78,119.13 A21.F1 48.51,119.13 43.43,119.13 A21.F2 42.16,119.13 37.08,119.13 A22.F1 35.81,119.13 30.73,119.13 A22.F2 29.46,119.13 24.38,119.13 A23.F1 23.11,119.13 18.03,119.13 A23.F2 | v61.98,84.07 59.44,84.07 A20.U2 | v49.28,84.07 46.74,84.07 A21.U2 | A20.R2 54.86,93.73 49.78,93.73 A21.R1 | v60.71,109.47 64.52,109.47 A20.K1 | v60.2,106.93 56.13,106.93 A20.L2 | A20.N1 61.21,100.08 56.13,100.08 A20.N2 | v36.58,84.07 34.04,84.07 A22.U2 | A21.R2 42.16,93.73 37.08,93.73 A22.R1 | v39.62,106.43 42.16,106.43 A21.L2 | v23.88,84.07 21.34,84.07 A23.U2 | A22.R2 29.46,93.73 24.38,93.73 A23.R1 | v26.92,106.43 29.46,106.43 A22.L2 | v11.18,84.07 8.64,84.07 A24.U2 | A24.R2 5.33,93.73 10.41,93.73 A24.R1 11.68,93.73 16.76,93.73 A23.R2 | v14.22,106.43 16.76,106.43 A23.L2 | A24.F1 10.41,119.13 5.33,119.13 A24.F2 | 284.61,118.24 284.73,118.11 288.8,118.11 289.56,117.35 291.59,117.35 293.37,119.13 296.16,119.13 A01.F2
  Bottom 1.27: 284.61,118.24 284.48,118.36 A02.F2 | 259.21,118.24 259.33,118.11 263.4,118.11 264.16,117.35 266.19,117.35 267.97,119.13 270.76,119.13 A03.F2 272.03,119.13 275.08,119.13 276.86,117.35 278.89,117.35 279.4,117.86 284.23,117.86 284.61,118.24 | 259.21,118.24 259.08,118.36 A04.F2 | 233.81,118.24 233.93,118.11 238,118.11 238.76,117.35 240.79,117.35 242.57,119.13 245.36,119.13 A05.F2 246.63,119.13 249.68,119.13 251.46,117.35 253.49,117.35 254,117.86 258.83,117.86 259.21,118.24 | 233.81,118.24 233.68,118.36 A06.F2 | 208.41,118.24 208.53,118.11 212.6,118.11 213.36,117.35 215.39,117.35 217.17,119.13 219.96,119.13 A07.F2 221.23,119.13 224.28,119.13 226.06,117.35 228.09,117.35 228.6,117.86 233.43,117.86 233.81,118.24 | 208.41,118.24 208.28,118.36 A08.F2 | 183.01,118.24 183.13,118.11 187.2,118.11 187.96,117.35 189.99,117.35 191.77,119.13 194.56,119.13 A09.F2 195.83,119.13 198.88,119.13 200.66,117.35 202.69,117.35 203.2,117.86 208.03,117.86 208.41,118.24 | 183.01,118.24 182.88,118.36 A10.F2 | v168.66,128.52 172.47,128.52 A11.C2 | v125.48,84.07 122.94,84.07 A15.U2 | A15.R2 119.63,93.73 124.71,93.73 A15.R1 | A15.F1 124.71,119.13 119.63,119.13 A15.F2 | 183.01,118.24 182.63,117.86 177.8,117.86 177.29,117.35 175.26,117.35 173.48,119.13 170.43,119.13 A11.F2 | v96.77,70.1 v90.42,70.1
N$1  (via drill 0.61)
  Top 0.305: v106.68,120.65 106.68,121.41 106.43,121.67 106.43,124.71 A16.D2 | v101.6,120.4 101.6,117.35 101.35,117.09 v101.35,114.3 | v97.03,114.05 97.03,112.52 96.77,112.27 96.77,110.24 A17.K2
  15 0.305: v87.12,115.57 92.2,110.49 v92.2,110.24
  Bottom 0.305: v87.12,115.57 86.87,115.82 84.84,115.82 A18.H2 | v92.2,110.24 92.46,110.49 96.27,110.49 96.52,110.24 A17.K2 | v106.68,120.65 104.65,120.65 104.39,120.4 v101.6,120.4 | v101.35,114.3 98.3,114.3 98.04,114.05 v97.03,114.05
N$2  (via drill 0.61)
  Top 0.305: v85.34,100.08 85.34,101.35 85.85,101.85 v85.85,102.87 | v88.9,102.87 90.42,101.35 91.69,101.35 92.2,101.85 v92.2,103.12 | v106.68,114.3 106.68,115.06 106.43,115.32 106.43,118.36 A16.F2 | v102.62,114.05 101.6,113.03 101.6,111 101.35,110.74 101.35,107.95 101.6,107.7 101.6,104.65 101.35,104.39 v101.35,103.63
  Bottom 0.305: v85.34,100.08 81.53,100.08 A18.N2 | v85.85,102.87 v88.9,102.87 | v92.2,103.12 96.27,103.12 A17.M2 97.28,103.89 101.09,103.89 v101.35,103.63 | v106.68,114.3 104.65,114.3 104.39,114.05 v102.62,114.05
N$3  (via drill 0.61)
  Top 0.305: v88.65,84.07 88.65,85.6 88.9,85.85 88.9,88.65 88.65,88.9 88.65,91.95 88.9,92.2 v88.9,92.96 | v91.69,92.96 91.69,95 92.2,95.5 v92.2,96.77 | v107.95,98.04 107.95,101.35 107.7,101.6 107.7,104.39 107.95,104.65 107.95,107.7 106.43,109.22 106.43,112.01 A16.J2
  Bottom 0.305: v88.65,84.07 84.84,84.07 A18.U2 | v88.9,92.96 v91.69,92.96 | v92.2,96.77 96.27,96.77 A17.P2 97.28,97.54 97.54,97.79 101.09,97.79 101.85,98.55 104.39,98.55 104.9,98.04 v107.95,98.04
N$4  (via drill 0.61)
  Top 0.305: v71.37,112.27 71.37,115.32 A19.H2 | v99.06,102.87 99.06,101.09 98.81,100.84 98.81,100.58 98.55,100.33 98.55,99.57 98.81,99.31 98.81,95.5 96.77,93.47 96.77,91.19 A17.S2
  2 0.305: v102.62,105.66 101.85,105.66 v99.06,102.87
  15 0.305: v71.37,112.27 90.68,92.96 90.68,92.46 v92.71,90.42
  Bottom 0.305: v92.71,90.42 96.27,90.42 A17.S2 | v102.62,105.66 105.92,105.66 A16.L2
N$5  (via drill 0.61)
  Top 0.305: v95.25,98.55 95,98.3 95,95.25 95.25,95 95.25,92.2 93.73,90.68 93.73,87.88 A17.T2
  Bottom 0.305: A16.N2 105.66,100.08 102.36,100.08 100.84,98.55 v95.25,98.55 78.99,98.55 78.49,99.06 75.69,99.06 75.18,98.55 74.17,98.55 72.64,100.08 68.83,100.08 A19.N2
N$6  (via drill 0.61)
  Top 0.305: v71.37,77.98 71.37,83.57 A19.U2 | v93.73,77.98 93.73,80.26 A17.V2 | v101.6,93.73 101.6,91.95 101.35,91.69 101.35,88.9 101.6,88.65 101.6,85.6 101.35,85.34 101.35,82.55 101.6,82.3 v101.6,78.23
  Bottom 0.305: v71.37,77.98 71.63,78.23 80.01,78.23 80.26,77.98 v93.73,77.98 93.98,78.23 v101.6,78.23 | v101.6,93.73 105.66,93.73 A16.R2
N$7  (via drill 0.61)
  Top 0.305: A19.J2 68.33,112.01 68.33,109.22 69.85,107.7 69.85,104.65 69.6,104.39 69.6,101.6 71.37,99.82 71.37,97.54 A19.P2 | A18.J2 81.53,112.27 81.53,108.71 82.55,107.7 82.55,104.65 82.3,104.39 82.3,101.6 84.07,99.82 84.07,97.54 A18.P2 | A18.V2 81.03,80.26 81.03,79.25 v80.77,78.99 81.03,78.74 81.03,71.88 v80.77,71.63 | v125.48,70.1 125.48,62.48 B15.B1 | v69.85,96.77 69.85,91.95 69.6,91.69 69.6,88.9 69.85,88.65 69.85,85.6 69.34,85.09 69.34,82.04 A19.V2
  Bottom 0.305: A18.P2 83.82,97.54 83.57,97.79 78.74,97.79 78.23,98.3 75.95,98.3 75.44,97.79 73.91,97.79 73.66,97.54 71.88,97.54 A19.P2 70.87,96.77 v69.85,96.77 | v80.77,78.99 72.14,78.99 70.1,81.03 68.83,81.03 A19.V2 | v125.48,70.1 125.22,69.85 104.9,69.85 103.38,71.37 97.79,71.37 97.54,71.63 91.44,71.63 91.19,71.88 81.03,71.88 v80.77,71.63
N_3CYCLE  (via drill 0.61)
  Top 0.305: 185.67,69.85 185.67,67.06 184.4,65.79 184.4,44.45 185.67,43.18 185.67,40.39 B10.K2 | 185.67,69.85 185.67,81.28 184.4,82.55 184.4,104.39 185.67,105.66 185.67,108.97 A10.K2 | v104.9,46.74 104.9,38.35 104.39,37.85 104.39,34.29 103.89,33.78 B17.M1 | v107.7,46.99 107.7,47.5 107.95,47.75 107.95,50.55 107.7,50.8 107.7,53.85 107.95,54.1 v107.95,56.9 | v116.33,60.45 116.59,60.71 v116.59,62.23 | v118.62,64.52 118.36,64.77 118.36,71.12 121.92,74.68 125.22,74.68 v125.22,73.66 | v185.93,69.85 185.67,69.85
  2 0.305: v116.59,62.23 116.59,62.48 v118.62,64.52
  15 0.305: v154.69,74.17 156.46,74.17 161.29,69.34 v163.07,69.34
  Bottom 0.305: v104.9,46.74 107.44,46.74 v107.7,46.99 | v107.95,56.9 111,56.9 114.55,60.45 v116.33,60.45 | v125.22,73.66 125.48,73.41 137.16,73.41 137.67,72.9 147.07,72.9 148.59,74.42 151.64,74.42 151.89,74.17 v154.69,74.17 | v163.07,69.34 165.61,69.34 166.12,69.85 177.29,69.85 177.55,69.6 183.13,69.6 183.39,69.85 v185.93,69.85
N_AC00  (via drill 0.61)
  Top 0.305: v114.05,70.87 114.05,63.5 114.3,63.25 114.3,60.45 112.78,58.93 112.78,56.13 B16.D1 | v157.99,74.17 v157.99,69.85 | v239.27,73.66 239.52,73.41 239.52,65.53 239.01,65.02 v239.01,63.5 | v241.3,125.48 241.3,123.7 241.05,123.44 v241.05,120.65 | v228.6,120.4 228.6,117.35 228.35,117.09 228.35,114.3 228.6,114.05 228.6,111 228.35,110.74 228.35,107.95 228.6,107.7 228.6,104.65 228.35,104.39 228.35,101.6 228.6,101.35 v228.6,98.04 | v225.55,98.04 225.55,82.55 224.54,81.53 224.54,75.18 v224.79,74.93
  2 0.305: v239.01,63.5 240.03,63.5 246.63,56.9 246.63,56.13 B05.D2
  Bottom 0.305: v114.05,70.87 114.3,70.61 124.46,70.61 124.97,71.12 125.98,71.12 127.25,69.85 v157.99,69.85 | v157.99,74.17 158.24,74.42 165.86,74.42 166.37,74.93 176.28,74.93 176.53,75.18 224.79,75.18 | 224.79,75.18 232.41,75.18 233.93,73.66 234.95,73.66 235.2,73.91 239.01,73.91 v239.27,73.66 | v241.3,125.48 245.36,125.48 A05.D2 | v241.05,120.65 238,120.65 237.74,120.4 234.95,120.4 234.7,120.65 231.65,120.65 231.39,120.4 v228.6,120.4 | v225.55,98.04 v228.6,98.04 | 224.79,75.18 v224.79,74.93
N_AC01  (via drill 0.61)
  Top 0.305: v267.46,66.8 267.21,67.06 267.21,78.74 267.46,78.99 267.46,82.3 v267.72,82.55 | v247.65,107.7 247.4,107.95 247.4,111 247.65,111.25 247.65,114.05 247.4,114.3 247.4,117.35 249.17,119.13 249.17,121.67 A05.E2 | v116.59,56.13 116.59,52.83 B16.E1 | v152.15,52.32 152.15,53.85 152.4,54.1 152.4,56.9 152.15,57.15 152.15,60.2 152.4,60.45 v152.4,62.23 | v199.39,42.67 199.39,43.18 200.66,44.45 200.66,46.23 v200.91,46.48 | v248.41,47.5 249.17,48.26 249.17,51.82 B05.E2
  2 0.305: v116.59,56.13 122.17,50.55 123.7,50.55 124.46,51.31 124.71,51.05 126.24,51.05 126.75,51.56 126.75,52.58 127.76,53.59 127.76,54.61 133.6,60.45 135.38,60.45 135.89,59.94 139.45,59.94 140.21,60.71 140.46,60.45 142.24,60.45 v150.37,52.32
  15 0.305: v267.72,82.55 267.72,82.8 266.45,84.07 266.45,86.11 266.95,86.61 266.7,86.87 266.7,87.63 261.87,92.46 261.37,92.46 260.35,93.47 260.35,95 255.78,99.57 255.78,100.08 254.51,101.35 254,101.35 v247.65,107.7 | v154.69,62.23 155.96,63.5 158.5,63.5 163.83,58.17 164.08,58.17 168.66,53.59 171.2,53.59 171.96,54.36 172.21,54.1 174.5,54.1 175.01,53.59 177.55,53.59 178.31,54.36 178.56,54.1 180.85,54.1 181.36,53.59 183.9,53.59 184.66,54.36 184.91,54.1 187.2,54.1 190.25,51.05 191.01,51.05 v199.39,42.67 | v217.17,47.75 218.95,47.75 219.46,47.24 222,47.24 223.27,48.51 228.35,43.43 228.6,43.43 v229.62,42.42
  Bottom 0.305: v267.46,66.8 260.1,66.8 260.1,65.53 256.79,62.23 256.03,62.23 250.7,56.9 250.44,56.9 250.44,54.61 249.68,53.85 249.68,53.09 B05.E2 | v152.15,52.32 v150.37,52.32 | v154.69,62.23 v152.4,62.23 | v200.91,46.48 201.42,46.99 202.18,46.99 202.44,47.24 202.69,47.24 203.2,47.75 v217.17,47.75 | v229.62,42.42 231.9,42.42 232.92,41.4 233.68,41.4 233.93,41.66 235.46,41.66 238.25,44.45 241.05,44.45 241.3,44.2 244.35,44.2 247.65,47.5 v248.41,47.5
N_AC02  (via drill 0.61)
  Top 0.305: v249.17,111.25 249.17,115.32 A05.H2 | v238.25,110.74 238.25,93.22 239.27,92.2 v239.27,88.9 | v230.89,82.3 231.14,82.04 231.14,67.82 v230.89,67.56 | v112.78,53.09 112.78,49.78 B16.F1 | v95.25,100.08 95.25,101.35 95,101.6 95,104.65 95.25,104.9 95.25,107.7 95,107.95 95,111 95.25,111.25 95.25,114.05 95,114.3 95,117.35 96.52,118.87 v96.52,120.65 | v139.45,97.03 139.45,98.3 139.7,98.55 v139.7,99.82 | v148.59,93.98 148.84,94.23 148.84,95 149.35,95.5 v149.35,102.62 | v158.5,102.62 158.5,104.65 158.75,104.9 v158.75,106.43
  2 0.305: v230.89,67.56 235.71,62.74 236.22,62.74 237.74,61.21 237.74,60.2 239.27,58.67 239.27,58.17 249.68,47.75 249.68,46.74 B05.H2 | v112.52,60.2 115.32,57.4 117.35,57.4 v121.41,61.47
  15 0.305: v112.78,53.09 114.3,54.61 114.3,55.88 109.73,60.45 v109.22,60.45 | v121.41,61.47 121.41,62.48 119.63,64.26 119.63,66.55 115.06,71.12 115.06,80.52 113.03,82.55 111,82.55 109.98,81.53 98.04,93.47 98.04,95 98.81,95.76 98.55,96.01 98.55,97.03 95.5,100.08 v95.25,100.08 | v96.52,120.65 100.08,117.09 101.35,117.09 102.11,117.86 102.36,117.6 104.65,117.6 106.93,115.32 107.19,115.32 107.7,114.81 107.7,114.3 109.22,112.78 109.22,111.76 109.73,111.25 110.24,111.25 v114.3,107.19 | v122.43,107.95 122.43,107.44 125.48,104.39 126.75,104.39 127.51,105.16 127.76,104.9 129.03,104.9 136.65,97.28 v136.65,96.77 | v139.7,99.82 140.97,98.55 142.24,98.55 144.53,96.27 144.78,96.27 147.07,93.98 v148.59,93.98 | v158.75,106.43 160.27,104.9 160.78,104.9 v166.12,99.57 | v180.09,100.33 183.9,96.52 183.9,95.76 186.44,93.22 186.69,93.22 188.21,91.69 188.21,91.19 189.48,89.92 189.74,89.92 190.25,89.41 190.25,89.15 v191.77,87.63
  Bottom 0.305: v249.17,111.25 241.3,111.25 240.79,110.74 v238.25,110.74 | v239.27,88.9 238,88.9 236.98,87.88 235.97,87.88 234.95,86.87 234.95,85.85 234.44,85.34 | 234.44,85.34 231.39,82.3 v230.89,82.3 | v109.22,60.45 112.27,60.45 v112.52,60.2 | v114.3,107.19 114.55,107.44 116.84,107.44 117.35,107.95 v122.43,107.95 | v136.65,96.77 136.91,97.03 v139.45,97.03 | v149.35,102.62 149.61,102.36 152.4,102.36 152.65,102.11 153.16,102.11 153.42,101.85 154.69,101.85 155.45,102.62 v158.5,102.62 | v166.12,99.57 168.4,99.57 169.42,98.55 176.53,98.55 176.78,98.81 178.56,98.81 v180.09,100.33 | v191.77,87.63 192.53,86.87 193.8,86.87 194.82,85.85 199.39,85.85 200.66,84.58 202.18,84.58 204.47,86.87 205.99,86.87 206.76,86.11 207.26,86.11 207.52,85.85 214.88,85.85 215.65,86.61 217.42,86.61 217.68,86.87 219.2,86.87 220.22,85.85 227.33,85.85 227.58,86.11 228.09,86.11 228.85,86.87 230.38,86.87 231.9,85.34 234.44,85.34
N_AC03  (via drill 0.61)
  Top 0.305: A05.K2 249.17,108.97 249.17,105.66 247.9,104.39 247.9,82.55 249.17,81.28 249.17,67.06 250.7,65.53 250.7,44.7 249.17,43.18 249.17,40.39 B05.K2 | v115.82,43.18 115.82,45.47 B16.H1 | v74.17,65.53 74.42,65.79 74.42,70.61 73.91,71.12 73.91,79.5 v72.39,81.03 | v35.56,116.08 35.56,118.11 35.05,118.62 v35.05,141.73 | v112.78,122.43 114.3,123.95 v114.3,124.71 | v163.83,117.09 163.83,115.32 165.1,114.05 v165.1,111.51 | v186.94,112.27 186.94,114.05 187.45,114.55 v187.45,115.82 | v198.37,117.6 199.64,118.87 199.64,120.4 200.15,120.9 v200.15,122.94
  2 0.305: v91.95,43.18 91.44,43.18 88.65,45.97 88.65,47.5 89.15,48.01 88.9,48.26 88.9,50.55 83.31,56.13 83.31,57.66 75.44,65.53 v74.17,65.53 | v92.2,141.73 93.73,140.21 93.73,139.7 95.5,137.92 97.28,137.92 v112.78,122.43
  15 0.305: v115.82,43.18 114.55,41.91 113.79,41.91 111.76,39.88 111.76,38.86 v112.52,38.1 | v106.43,38.1 104.65,38.1 104.14,37.59 103.89,37.85 101.6,37.85 101.35,38.1 99.06,38.1 98.55,38.61 98.55,39.88 97.03,41.4 95.25,41.4 94.49,40.64 94.23,40.89 93.73,40.89 91.95,42.67 v91.95,43.18 | v72.39,81.03 72.14,81.03 64.52,88.65 63.5,88.65 36.07,116.08 v35.56,116.08 | v135.64,123.95 135.89,123.95 139.19,120.65 139.45,120.65 139.95,120.14 140.21,120.14 141.99,118.36 v141.99,118.11 | v232.41,123.95 241.3,115.06 241.81,115.06 246.13,110.74 247.9,110.74 248.67,109.98 A05.K2
  Bottom 0.305: v112.52,38.1 111,38.1 110.74,37.85 107.95,37.85 107.7,38.1 v106.43,38.1 | v35.05,141.73 35.31,141.48 47.75,141.48 48.51,140.72 52.32,140.72 53.59,141.99 91.95,141.99 v92.2,141.73 | v114.3,124.71 114.55,124.46 118.11,124.46 118.62,123.95 123.95,123.95 124.71,123.19 125.73,123.19 128.02,120.9 129.29,120.9 130.81,122.43 132.33,122.43 133.86,123.95 v135.64,123.95 | v141.99,118.11 143.51,118.11 144.02,117.6 161.54,117.6 162.05,117.09 v163.83,117.09 | v165.1,111.51 169.16,111.51 169.42,111.25 182.88,111.25 183.13,111.51 186.18,111.51 v186.94,112.27 | v187.45,115.82 187.71,116.08 190.25,116.08 192.02,117.86 194.56,117.86 194.82,117.6 v198.37,117.6 | v200.15,122.94 200.41,123.19 202.18,123.19 202.44,123.44 203.96,123.44 204.47,123.95 v232.41,123.95
N_AC04  (via drill 0.61)
  Top 0.305: v212.09,68.58 211.84,68.83 211.84,81.79 212.85,82.8 212.85,85.09 212.34,85.6 212.34,88.65 212.85,89.15 v212.85,101.6 | v112.78,39.37 112.78,42.16 B16.J1 | v129.79,30.73 129.79,31.5 130.3,32 v130.3,33.78 | v161.54,23.88 161.54,25.15 162.05,25.65 162.05,30.48 162.31,30.73 162.31,31.24 162.81,31.75 162.81,33.53 v163.83,34.54 | v167.64,37.85 v167.64,35.05
  2 0.305: 235.97,44.2 215.65,64.52 215.65,65.02 v212.09,68.58 | 235.97,44.2 247.4,32.77 248.67,32.77 B05.M2 | v236.22,44.45 235.97,44.2
  15 0.305: v122.17,31.5 v114.3,39.37 | v136.4,36.32 147.57,25.15 149.1,25.15 149.61,25.65 149.86,25.4 152.15,25.4 152.4,25.15 155.45,25.15 155.96,25.65 156.21,25.4 158.24,25.4 v159.77,23.88
  Bottom 0.305: v212.85,101.6 215.65,101.6 215.9,101.35 218.95,101.35 219.2,101.6 222,101.6 222.25,101.35 225.3,101.35 225.55,101.6 228.35,101.6 228.6,101.35 231.65,101.35 231.9,101.6 234.7,101.6 234.95,101.35 238,101.35 238.25,101.6 241.05,101.6 241.3,101.35 244.35,101.35 246.13,103.12 248.67,103.12 A05.M2 | v114.3,39.37 v112.78,39.37 | v122.17,31.5 123.7,31.5 123.95,31.75 126.75,31.75 127.76,30.73 v129.79,30.73 | v130.3,33.78 131.06,34.54 132.59,34.54 134.37,36.32 v136.4,36.32 | v161.54,23.88 v159.77,23.88 | v163.83,34.54 164.85,34.54 165.35,35.05 v167.64,35.05 | v167.64,37.85 168.15,37.85 168.4,38.1 171.2,38.1 171.45,37.85 174.5,37.85 174.75,38.1 177.55,38.1 177.8,37.85 180.85,37.85 181.1,38.1 183.9,38.1 184.15,37.85 187.2,37.85 187.45,38.1 190.25,38.1 190.5,37.85 193.55,37.85 193.8,38.1 196.6,38.1 196.85,37.85 199.9,37.85 200.15,38.1 202.95,38.1 203.2,37.85 206.25,37.85 206.5,38.1 209.3,38.1 209.55,37.85 212.6,37.85 212.85,38.1 215.65,38.1 215.9,37.85 218.95,37.85 225.55,44.45 228.35,44.45 229.11,43.69 231.65,43.69 232.41,44.45 v236.22,44.45
N_AC05  (via drill 0.61)
  Top 0.305: v248.41,30.73 248.41,30.48 249.17,29.72 249.17,27.69 B05.P2 | v214.63,64.52 214.88,64.77 v214.88,67.31 | v218.19,67.31 218.44,67.56 218.44,80.01 218.69,80.26 218.69,82.3 219.2,82.8 v219.2,91.69 | v137.92,57.91 139.45,59.44 139.45,60.2 139.7,60.45 139.7,63.25 139.45,63.5 v139.45,76.2 | v151.38,78.99 v151.38,76.2 | v188.21,63.5 187.96,63.75 187.96,67.56 v188.21,67.82
  2 0.305: v214.63,64.52 v248.41,30.73 | v127,40.89 129.29,43.18 129.79,43.18 133.1,46.48 133.1,47.5 133.6,48.01 133.35,48.26 133.35,50.55 133.1,50.8 133.1,53.34 135.64,55.88 135.89,55.88 v137.92,57.91 | v163.58,66.8 v151.38,78.99
  Bottom 0.305: v218.19,67.31 v214.88,67.31 214.63,67.06 204.98,67.06 204.22,67.82 v188.21,67.82 | v219.2,91.69 222,91.69 222.5,92.2 227.33,92.2 227.58,92.46 227.84,92.46 229.62,94.23 231.9,94.23 232.92,95.25 234.7,95.25 234.95,95 238,95 238.25,95.25 241.05,95.25 241.3,95 244.35,95 246.13,96.77 248.67,96.77 A05.P2 | v127,40.89 123.95,40.89 123.44,41.4 120.9,41.4 120.4,40.89 116.84,40.89 116.33,40.39 B16.K1 | v139.45,76.2 139.7,76.45 151.13,76.45 v151.38,76.2 | v163.58,66.8 170.94,66.8 171.45,66.29 172.47,66.29 172.72,66.55 176.02,66.55 178.82,63.75 183.64,63.75 184.15,63.25 187.2,63.25 187.45,63.5 v188.21,63.5
N_AC06  (via drill 0.61)
  Top 0.305: 250.44,21.59 249.94,21.08 B05.S2 | 250.44,21.59 250.44,25.15 250.95,25.65 250.95,43.18 251.21,43.43 251.21,44.2 251.46,44.45 251.46,46.74 v252.22,47.5 | v238.51,67.56 238.76,67.82 238.76,72.64 238.25,73.15 238.25,74.93 238.51,75.18 238.51,76.2 238,76.71 238,81.28 239.01,82.3 239.01,85.09 v239.27,85.34 | v242.32,85.85 v242.32,88.65 | v113.03,33.27 113.28,33.53 113.28,36.07 B16.L1 | v117.09,29.21 117.09,28.7 117.6,28.19 117.6,25.4 117.09,24.89 v117.09,23.88 | v165.61,10.16 166.88,8.89 166.88,4.83 170.69,1.02 213.36,1.02 v213.36,6.6 | v250.44,7.11 250.44,12.45 250.95,12.95 250.95,15.24 250.44,15.75 250.44,21.59
  2 0.305: v117.09,29.21 v113.03,33.27
  15 0.305: v252.22,47.5 247.4,52.32 247.4,53.85 247.65,54.1 247.65,56.9 241.05,63.5 241.05,65.02 v238.51,67.56 | v117.09,23.88 117.09,22.1 120.65,18.54 120.65,18.29 121.92,17.02 122.68,17.02 124.46,15.24 125.98,15.24 126.75,14.48 126.75,14.22 139.95,1.02 155.7,1.02 160.02,5.33 160.78,5.33 v165.61,10.16
  Bottom 0.305: v239.27,85.34 241.05,85.34 241.55,85.85 v242.32,85.85 | v242.32,88.65 244.35,88.65 246.13,90.42 248.67,90.42 A05.S2 | v213.36,6.6 213.61,6.35 223.77,6.35 224.28,6.86 232.66,6.86 232.92,7.11 v250.44,7.11
N_AC07  (via drill 0.61)
  Top 0.305: A05.T2 246.13,86.61 246.13,83.31 247.4,82.04 247.4,79.25 246.13,77.98 246.13,63.75 247.4,62.48 247.4,22.1 246.13,20.83 246.13,18.03 B05.T2 246.13,16.76 246.13,15.49 246.89,14.73 246.89,13.21 247.65,12.45 v247.65,8.13 | v115.82,28.96 115.82,32.77 B16.M1 | v116.08,25.15 114.3,23.37 114.3,22.1 114.05,21.84 v114.05,20.57 | v193.29,10.41 193.29,12.45 194.31,13.46 v194.31,13.97
  2 0.305: v115.82,28.96 117.6,27.18 117.6,26.67 v116.08,25.15 | v114.05,20.57 114.05,19.56 132.59,1.02 155.7,1.02 159,4.32 180.09,4.32 183.64,7.87 184.15,7.87 185.42,9.14 189.23,9.14 v190.5,10.41
  15 0.305: v194.31,13.97 196.85,13.97 202.18,8.64 213.36,8.64 v214.63,7.37
  Bottom 0.305: v193.29,10.41 v190.5,10.41 | v214.63,7.37 214.88,7.11 223.52,7.11 224.03,7.62 232.41,7.62 232.66,7.87 247.4,7.87 v247.65,8.13
N_AC08  (via drill 0.61)
  Top 0.305: A05.V2 245.36,80.52 244.6,79.76 v244.6,25.15 244.6,16 246.13,14.48 246.13,11.68 B05.V2 | v104.9,20.32 104.9,12.7 104.39,12.19 v104.39,8.13 | v92.96,3.56 v92.96,8.13 | v30.73,7.87 v30.73,3.05 | v19.05,7.87 19.05,12.45 18.8,12.7 18.8,15.75 19.05,16 19.05,18.8 18.8,19.05 18.8,22.1 19.05,22.35 19.05,25.15 18.8,25.4 18.8,28.45 19.05,28.7 19.05,31.5 18.8,31.75 18.8,34.8 19.05,35.05 19.05,37.85 18.8,38.1 18.8,41.15 19.05,41.4 19.05,44.2 18.8,44.45 18.8,47.5 19.05,47.75 19.05,50.55 18.8,50.8 18.8,53.85 19.05,54.1 19.05,56.9 18.8,57.15 18.8,60.2 19.05,60.45 19.05,63.25 17.27,65.02 v17.27,79.25 | v2.03,126.75 1.78,127 1.78,138.68 v2.03,138.94 | v41.66,136.14 v41.66,138.94
  2 0.305: v110.24,23.37 110.24,23.11 109.47,22.35 108.97,22.35 107.19,20.57 107.19,20.07 106.68,19.56 105.66,19.56 v104.9,20.32 | v49.53,135.38 49.78,135.38 52.07,137.67 52.32,137.41 64.77,137.41 71.12,131.06 73.41,131.06 78.49,125.98 78.49,124.46 85.85,117.09 88.65,117.09 90.17,118.62 v90.42,118.36 | v150.11,75.44 150.62,75.44 155.45,70.61 157.23,70.61 157.48,70.87 158.5,70.87 162.56,66.8 162.56,66.29 170.94,57.91 171.96,57.91 172.47,57.4 172.47,56.9 181.1,48.26 181.61,48.26 v206.25,23.62
  15 0.305: v110.24,23.37 111.76,21.84 112.78,21.84 114.3,23.37 114.3,25.15 112.27,27.18 112.27,29.46 B16.N1 | v17.27,79.25 15.49,81.03 15.49,82.3 16.26,83.06 16,83.31 16,85.6 9.91,91.69 9.91,92.71 4.32,98.3 4.32,98.55 1.02,101.85 1.02,125.73 v2.03,126.75 | v90.42,118.36 91.19,117.6 91.95,117.6 99.06,110.49 99.31,110.49 104.39,105.41 104.39,104.65 105.66,103.38 105.66,102.36 106.43,101.6 106.68,101.6 111.25,97.03 111.25,95.25 110.74,94.74 110.74,93.73 128.27,76.2 131.06,76.2 v132.08,75.18
  Bottom 0.305: v104.39,8.13 104.14,8.38 93.22,8.38 v92.96,8.13 | v92.96,3.56 92.71,3.3 60.96,3.3 60.45,3.81 59.44,3.81 58.17,2.54 34.8,2.54 34.29,3.05 v30.73,3.05 | v30.73,7.87 30.48,7.62 19.3,7.62 v19.05,7.87 | v2.03,138.94 22.86,138.94 23.11,138.68 41.4,138.68 v41.66,138.94 | v41.66,136.14 41.91,136.4 43.94,136.4 44.2,136.65 48.01,136.65 49.28,135.38 v49.53,135.38 | v132.08,75.18 132.33,74.93 139.7,74.93 140.46,75.69 149.86,75.69 v150.11,75.44 | v206.25,23.62 207.52,22.35 214.63,22.35 214.88,22.61 215.14,22.61 216.92,24.38 219.2,24.38 220.22,25.4 222,25.4 222.25,25.15 225.3,25.15 225.55,25.4 228.35,25.4 228.6,25.15 231.65,25.15 231.9,25.4 234.7,25.4 234.95,25.15 238,25.15 238.25,25.4 241.05,25.4 241.3,25.15 v244.6,25.15
N_AC09  (via drill 0.61)
  Top 0.305: A06.D2 233.43,124.71 233.43,121.41 231.9,119.89 231.9,61.47 233.43,59.94 233.43,56.13 B06.D2 | v186.94,10.41 186.94,12.45 187.45,12.95 187.45,15.24 186.94,15.75 186.94,18.8 187.45,19.3 187.45,30.48 187.71,30.73 v187.71,32.77 | v212.34,35.05 212.34,36.58 213.61,37.85 213.61,40.13 214.12,40.64 v214.12,40.89
  2 0.305: v154.69,5.59 154.69,6.86 155.45,7.62 169.42,7.62 170.69,6.35 181.1,6.35 183.39,8.64 183.9,8.64 184.66,9.4 v184.66,10.41
  15 0.305: v121.92,28.7 122.43,28.7 133.35,17.78 133.35,17.02 v134.37,16 | v141.99,16 142.24,16 152.15,6.1 154.18,6.1 v154.69,5.59 | v187.71,32.77 188.72,32.77 190.25,34.29 190.25,34.8 v191.52,36.07 | v231.14,50.55 232.41,51.82 232.41,54.36 232.92,54.86 B06.D2
  Bottom 0.305: v121.92,28.7 120.9,28.7 120.4,28.19 116.84,28.19 116.33,27.69 B16.P1 | v141.99,16 v134.37,16 | v186.94,10.41 v184.66,10.41 | v191.52,36.07 191.77,35.81 193.55,35.81 194.06,35.31 194.56,35.31 194.82,35.05 v212.34,35.05 | v214.12,40.89 215.65,40.89 217.17,42.42 218.69,42.42 219.2,42.93 219.2,43.43 226.57,50.8 228.35,50.8 228.6,50.55 v231.14,50.55
N_AC10  (via drill 0.61)
  Top 0.305: v114.3,3.05 114.3,12.45 114.05,12.7 114.05,15.49 114.3,15.75 114.3,18.8 112.78,20.32 112.78,23.11 B16.R1 | v160.27,6.35 v160.27,2.03 | v237.74,4.32 237.74,12.45 238.25,12.95 238.25,43.18 238.51,43.43 238.51,44.2 238.76,44.45 238.76,46.99 v239.01,47.24 | v236.73,47.75 236.73,49.28 236.47,49.53 236.47,51.82 B06.E2 | v234.95,114.3 234.7,114.55 234.7,117.09 234.95,117.35 234.95,117.86 236.47,119.38 236.47,121.67 A06.E2 | v215.9,114.05 215.9,111 215.65,110.74 215.65,107.95 215.9,107.7 215.9,104.65 215.65,104.39 215.65,101.6 215.9,101.35 215.9,98.3 215.65,98.04 215.65,95.25 215.9,95 215.9,92.2 214.63,90.93 v214.63,88.9 | v217.68,82.04 217.68,69.85 v217.42,69.6 | v230.89,56.13 231.14,55.88 v231.14,53.85
  2 0.305: v211.33,88.65 211.33,88.39 v217.68,82.04 | v230.89,56.13 v217.42,69.6
  Bottom 0.305: v114.3,3.05 119.89,3.05 121.16,1.78 156.46,1.78 156.97,2.29 160.02,2.29 v160.27,2.03 | v160.27,6.35 160.53,6.1 167.13,6.1 167.39,6.35 168.4,6.35 169.93,4.83 208.53,4.83 209.04,5.33 210.06,5.33 211.33,4.06 237.49,4.06 v237.74,4.32 | v239.01,47.24 238.25,47.24 237.74,47.75 v236.73,47.75 | v234.95,114.3 231.65,114.3 231.39,114.05 228.6,114.05 228.35,114.3 225.3,114.3 225.04,114.05 222.25,114.05 222,114.3 218.95,114.3 218.69,114.05 v215.9,114.05 | v214.63,88.9 212.6,88.9 212.34,88.65 v211.33,88.65 | v231.14,53.85 232.92,52.07 234.19,52.07 234.44,52.32 235.97,52.32 B06.E2
N_AC11  (via drill 0.61)
  Top 0.305: v117.09,7.37 117.09,12.19 117.6,12.7 117.6,15.49 117.09,16 117.09,19.81 116.59,20.32 B16.S1 | v225.04,5.08 225.04,12.45 225.55,12.95 v225.55,40.89 | v231.14,41.4 v231.14,44.7 | v236.22,111.25 236.22,112.78 236.47,113.03 236.47,115.32 A06.H2 | v200.15,110.74 200.15,82.55 199.14,81.53 199.14,67.31 v201.93,64.52
  2 0.305: v201.93,64.52 v225.55,40.89
  Bottom 0.305: v117.09,7.37 160.78,7.37 161.29,6.86 166.88,6.86 167.13,7.11 168.66,7.11 170.18,5.59 208.28,5.59 208.79,6.1 210.31,6.1 211.58,4.83 224.79,4.83 v225.04,5.08 | v225.55,40.89 228.35,40.89 228.85,41.4 v231.14,41.4 | v231.14,44.7 232.41,45.97 235.97,45.97 B06.H2 | v236.22,111.25 203.2,111.25 202.69,110.74 v200.15,110.74
N_ACCEPT  (via drill 0.61)
  Top 0.305: v135.13,29.72 135.13,30.23 134.87,30.48 134.87,32.77 B14.M2 | v153.42,11.43 153.16,11.18 153.16,5.33 v153.42,5.08 | v209.55,4.32 209.55,12.45 209.3,12.7 209.3,15.75 211.07,17.53 211.07,20.07 B08.S2 | v215.65,90.42 215.65,88.9 215.9,88.65 215.9,85.6 215.65,85.34 215.65,82.55 215.9,82.3 215.9,66.8 215.65,66.55 215.65,63.5 215.9,63.25 215.9,53.85 215.65,53.59 215.65,50.8 215.9,50.55 215.9,47.5 215.65,47.24 215.65,44.45 215.9,44.2 215.9,41.15 215.65,40.89 215.65,38.1 215.9,37.85 215.9,34.8 215.65,34.54 215.65,31.75 215.9,31.5 215.9,28.45 215.65,28.19 215.65,25.4 215.9,25.15 215.9,22.1 215.65,21.84 v215.65,20.57
  2 0.305: v153.42,11.43 v135.13,29.72
  Bottom 0.305: v153.42,5.08 153.92,4.57 162.56,4.57 163.07,4.06 209.3,4.06 v209.55,4.32 | v215.65,90.42 211.84,90.42 A08.S2 | v215.65,20.57 211.84,20.57 B08.S2
N_ACCLR  (via drill 0.61)
  Top 0.305: v231.9,26.92 232.16,27.18 232.16,29.46 231.9,29.72 231.9,30.48 232.16,30.73 232.16,35.81 231.9,36.07 231.9,36.83 232.16,37.08 232.16,42.16 231.9,42.42 231.9,43.18 232.16,43.43 232.16,48.51 231.9,48.77 231.9,49.53 232.16,49.78 232.16,54.86 231.9,55.12 v231.9,59.18 | v227.33,63.75 227.58,64.01 227.58,67.82 227.33,68.07 227.33,77.98 228.6,79.25 228.6,82.3 228.35,82.55 228.35,85.6 228.6,85.85 228.6,88.65 228.35,88.9 v228.35,90.17 228.35,91.95 228.6,92.2 v228.6,95 | v60.45,94.49 60.71,94.74 60.71,99.31 60.45,99.57 60.45,100.33 60.71,100.58 v60.71,102.87 | v63.5,107.19 63.5,107.7 63.25,107.95 63.25,117.35 63.5,117.6 v63.5,118.62 | v73.15,121.92 76.45,125.22 76.45,125.98 77.22,126.75 78.99,126.75 82.55,130.3 v82.55,131.06 | v85.34,131.06 85.34,133.1 85.85,133.6 v85.85,134.11 | v88.65,134.11 88.65,139.7 92.46,143.51 94.74,143.51 v94.74,140.21
  2 0.305: v227.33,63.75 v231.9,59.18 | v60.71,102.87 60.71,103.12 61.98,104.39 62.48,104.39 62.74,104.65 64.01,104.65 64.52,105.16 64.52,106.17 v63.5,107.19 | v66.29,118.62 66.29,118.87 65.02,120.14 65.02,120.4 63.25,122.17 63.25,123.44 66.8,127 68.58,127 73.15,122.43 v73.15,121.92 | v218.44,98.55 218.95,98.55 223.27,94.23 224.28,94.23 v228.35,90.17
  15 0.305: v60.45,94.49 61.21,95.25 62.23,95.25 78.23,79.25 78.23,78.23 87.63,68.83 87.63,64.52 88.9,63.25 88.9,60.96 89.15,60.71 88.65,60.2 88.65,58.67 89.92,57.4 94.49,57.4 100.58,51.31 100.58,49.78 B17.F1 | v123.7,130.05 v113.79,139.95 | v148.34,130.3 148.59,130.3 v180.09,98.81
  Bottom 0.305: v231.9,26.92 235.97,26.92 B06.P2 | v228.6,95 231.65,95 233.43,96.77 235.97,96.77 A06.P2 | v66.29,118.62 v63.5,118.62 | v85.34,131.06 v82.55,131.06 | v88.65,134.11 v85.85,134.11 | v94.74,140.21 95,140.46 113.28,140.46 v113.79,139.95 | v123.7,130.05 123.95,129.79 126.75,129.79 127.25,130.3 129.54,130.3 130.05,129.79 133.1,129.79 133.6,130.3 135.89,130.3 136.4,129.79 139.45,129.79 139.95,130.3 142.49,130.3 143,129.79 145.8,129.79 146.3,130.3 v148.34,130.3 | v180.09,98.81 181.86,98.81 182.12,98.55 189.48,98.55 190.25,99.31 190.75,99.31 191.01,99.57 193.8,99.57 194.82,98.55 195.58,98.55 195.83,98.81 197.1,98.81 197.87,99.57 200.15,99.57 201.17,98.55 v218.44,98.55
N_ADD00  (via drill 0.61)
  Top 0.305: v76.2,63.25 76.2,60.45 74.68,58.93 74.68,56.13 B19.D1 | v99.57,72.39 v99.57,63.5 | v156.72,71.63 156.97,71.88 v156.97,76.96 | v196.34,71.88 196.09,71.63 196.09,64.01 197.36,62.74 197.36,60.71 v197.61,60.45 | v200.91,59.94 v200.91,57.15 | v215.9,125.48 215.9,123.7 215.65,123.44 215.65,120.65 215.9,120.4 215.9,117.35 215.65,117.09 v215.65,115.32 | v177.8,114.05 177.8,111 177.55,110.74 177.55,107.95 177.8,107.7 177.8,104.65 177.55,104.39 177.55,101.6 178.05,101.09 178.05,96.27 179.83,94.49 v179.83,92.2 | v191.52,80.52 191.26,80.26 191.26,72.14 v191.52,71.88
  2 0.305: v191.52,80.52 v179.83,92.2
  15 0.305: v163.07,70.87 v156.97,76.96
